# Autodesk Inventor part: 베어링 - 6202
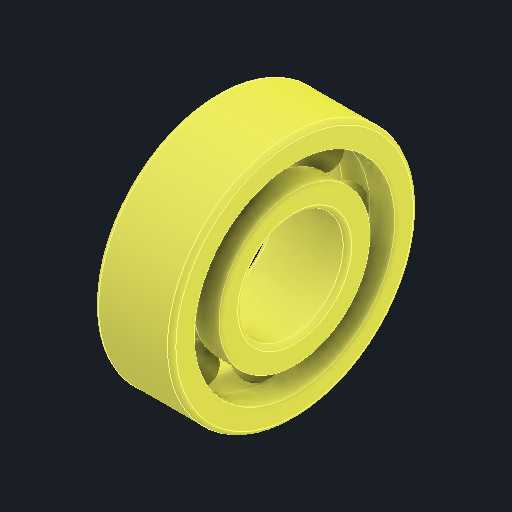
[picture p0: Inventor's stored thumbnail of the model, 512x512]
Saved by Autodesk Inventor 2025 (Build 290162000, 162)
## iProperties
Created: 2025-08
Part Number: 베어링 - 6202
Material: 강, 연강
Description: 깊은 그루브 볼 베어링
Document SubType Name: Modeling
Designer: infra14
Density: 7.86 g/cm^3
Appearance: 기본값
Author: jhkim
Sending System: Autodesk Inventor 2026
Preprocessor: ST-DEVELOPER v20.1
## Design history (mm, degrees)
feature "Solid1"
feature "Solid1:1"
feature "Solid1:2"
feature "Solid1:3"
feature "Solid1:4"
feature "Solid1:5"
feature "Solid1:6"
feature "Solid1:7"
feature "Solid1:8"
feature "Solid1:9"
node "솔리드1"
node "솔리드2"
node "솔리드3"
node "솔리드4"
node "솔리드5"
node "솔리드6"
node "솔리드7"
node "솔리드8"
node "솔리드9"
node "솔리드10"
